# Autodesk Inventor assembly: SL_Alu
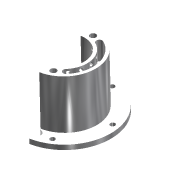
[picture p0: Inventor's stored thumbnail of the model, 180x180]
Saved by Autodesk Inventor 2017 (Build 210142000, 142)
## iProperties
Part Number: SL_Alu
Material: Generisch
Document SubType Name: Assembly
Designer: gabriel
Author: gabriel
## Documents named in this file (3)
- C:\Uni-Daten\Sprechmaschine\Demonstrator\Konstruktion\Stimmlippe\SL_Alu.iam
- C:\Uni-Daten\Sprechmaschine\Demonstrator\Konstruktion\Stimmlippe\SL_Alu_obererTeil.ipt
- C:\Uni-Daten\Sprechmaschine\Demonstrator\Konstruktion\Stimmlippe\SL_Alu_untererTeil.ipt
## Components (2 placed, 2 different names)
1. SL_Alu_obererTeil:1 — Passend:1
2. SL_Alu_untererTeil:1 — Passend:1
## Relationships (1: Mate 1)
- Passend:1 [Mate]: SL_Alu_obererTeil:1 ↔ SL_Alu_untererTeil:1
